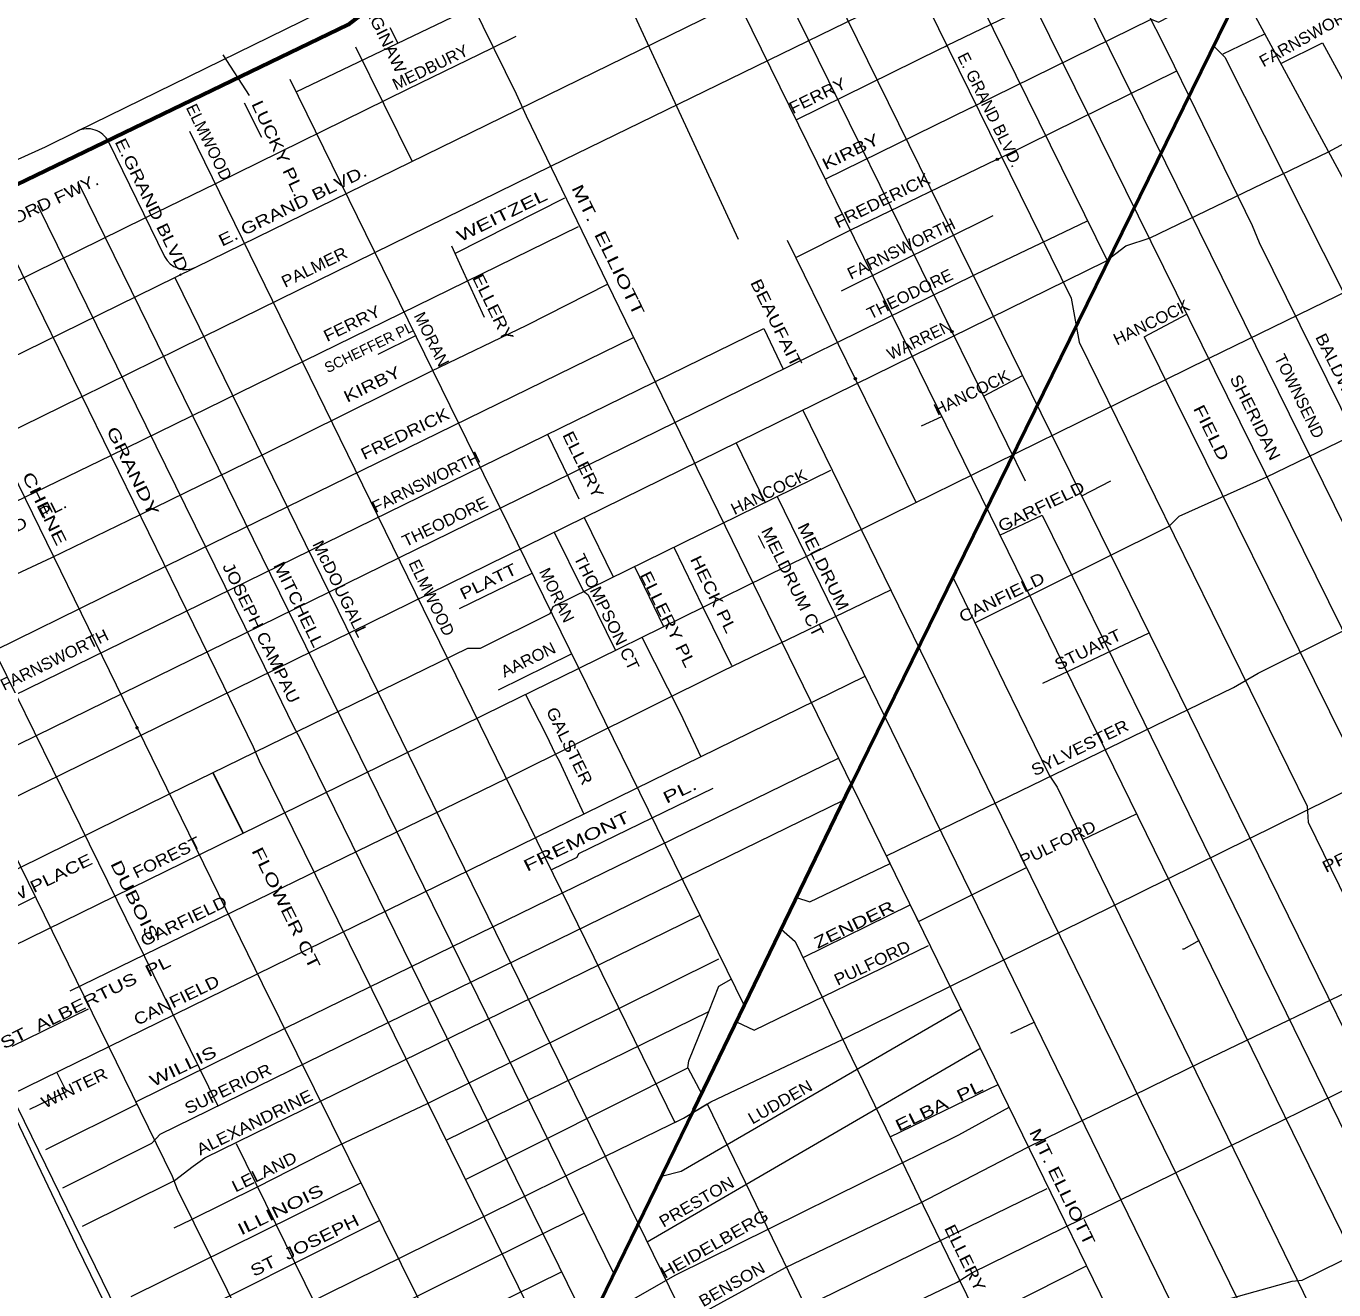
# Model space of a CAD drawing. Extents: x 34705 to 138605, y 34275 to 143551.
# Drawn here: x 100858 to 109243, y 108885 to 116985 of the extents above; entities that cross this region are included whole.
import ezdxf
from ezdxf.enums import TextEntityAlignment as Align

# ---------------------------------------------------------------- set-up
doc = ezdxf.new("R2010")
doc.units = 0
doc.header["$LTSCALE"] = 30
doc.header["$PDMODE"] = 32
doc.header["$PDSIZE"] = 15
for name, color, linetype, lineweight in [('1', 7, 'Continuous', 13), ('11', 7, 'Continuous', 13), ('50', 7, 'Continuous', 13), ('51', 7, 'Continuous', 35)]:
    doc.layers.add(name, color=color, linetype=linetype, lineweight=lineweight)

msp = doc.modelspace()

# ---------------------------------------------------------------- linework, layer by layer
at = {"layer": '1'}
for p, q in [((101946.58, 115440.18), (106331.92, 117586.09)), ((105661.1, 117328.25), (106793.71, 115026.96)), ((105968.83, 117341.08), (107047.11, 115150.16)), ((103190.96, 116977.68), (103241.23, 116876.22)), ((108533.25, 116808.59), (108799.8, 116935.24)), ((102290.54, 116540.81), (102122.04, 116800.93)), ((102969.6, 116852.85), (103333.34, 116118.77)), ((105794.39, 116385.29), (106718.61, 116839.15)), ((106718.61, 116839.15), (106749.55, 116854.35)), ((106719.59, 116839.12), (106749.76, 116853.93)), ((108902.55, 116745.01), (109169.81, 116878.68)), ((109169.81, 116878.68), (109748.55, 115811.65)), ((102548.95, 116644.61), (104007.06, 113672.22)), ((102256.05, 116494.16), (102366.55, 116273.1)), ((105981.35, 116004.43), (106913.98, 116461.76)), ((106913.98, 116461.76), (106937.02, 116473.06)), ((106914.97, 116461.73), (106937.23, 116472.64)), ((101904.66, 116312.82), (103353.47, 113354.48)), ((100112.7, 115818.14), (100981.9, 116212.44)), ((101386.15, 116243.47), (101745.94, 115508.93)), ((107084.73, 116131.92), (107100.92, 116139.73)), ((107085.73, 116131.9), (107101.12, 116139.32)), ((101196.3, 115973.74), (102650.04, 113012.5)), ((103607.65, 115527.11), (104312.09, 115885.41)), ((100930.19, 115838.63), (102383.21, 112882.78)), ((106086.97, 115288.74), (107058.8, 115771.9)), ((107368.04, 115596.43), (107663.35, 115738.12)), ((100679.08, 115705.99), (102123.39, 112756.47)), ((105738.03, 115614.35), (106173.86, 114725.62)), ((107363.16, 115594.08), (107368.04, 115596.43)), ((107364.18, 115594.07), (107368.24, 115596.02)), ((100130.13, 115432.56), (101569.9, 112487.39)), ((101811.9, 115374.28), (102907.45, 113137.64)), ((108027.16, 114992.93), (108300.55, 115138.4)), ((99058.1, 111852.89), (105587.02, 115047.35)), ((99606.19, 115114.96), (101026.13, 112223.03)), ((105587.01, 115047.35), (105712.39, 114787.06)), ((103354.21, 114999.3), (103112.73, 114881.18)), ((106793.71, 115026.96), (107264.3, 114070.8)), ((106173.86, 114725.62), (106563.86, 113930.38)), ((106996.77, 114614.39), (107246.52, 114744.99)), ((106599.07, 114424.3), (106728.43, 114482.53)), ((104200.41, 114368.91), (104402.66, 113956.36)), ((107626.19, 113973.56), (107813.85, 114070.66)), ((104436.21, 113835.46), (104621.95, 113454.92)), ((107101.51, 113722.51), (107372.9, 113850.14)), ((105552.22, 113719.92), (105592.95, 113638.07)), ((104007.06, 113672.22), (105461.73, 110706.87)), ((105010.3, 113645.36), (105196.3, 113260.42)), ((103637.05, 113252.79), (104101.73, 113479.25)), ((104757.89, 113521.58), (104944.02, 113136.38)), ((105196.3, 113260.42), (105380.59, 112886.54)), ((102907.45, 113137.64), (106147.78, 106522.3)), ((107377.4, 112773.99), (108057.88, 113096.43)), ((102650.04, 113012.5), (104626.36, 108986.77)), ((103887.28, 112730.34), (104355.65, 112961.63)), ((101026.13, 112223.03), (102086.57, 110063.28)), ((107632.42, 111771.01), (107976.75, 111937.08)), ((100540.44, 111219.2), (100915.56, 111404.1)), ((100768.13, 110446.98), (101256.95, 110685.64)), ((107172.27, 110529.93), (107320.76, 110600.97)), ((104839.84, 109192.55), (106972.96, 110430.97)), ((105100.6, 110307.27), (105190.82, 110139.11)), ((106397.62, 109865.98), (107089.92, 110200.3)), ((100725.09, 110119.47), (101179.79, 109170.78)), ((101531.27, 108841.79), (103003.94, 109570.01)), ((102010.55, 108172.35), (104435.15, 109376.27)), ((101179.4, 109171.09), (101613.2, 108281.84)), ((102173.49, 107956.97), (104290.98, 109001.05)), ((106967.75, 108690.6), (107657.67, 109038.06))]:
    msp.add_line(p, q, dxfattribs=at)
at = {"layer": '1', "lineweight": 53}
msp.add_lwpolyline([(101368.9, 103017.54), (102548.84, 105055.11), (103212.24, 106184.42), (103282.07, 106324.13), (104294.63, 108304.78), (105138.43, 110039.49), (106145.17, 112117.65), (109289.05, 118526.78), (110743.87, 121478.11), (113275.26, 126686.61), (116465.7, 133274.74), (120395.18, 141348.71), (121157.51, 142914.61), (121243.66, 143093.14)], dxfattribs=at)
at = {"layer": '1'}
for points in [[(97901.79, 110686.48), (98842.55, 111139.22), (98862.73, 111098.07), (107780.39, 115477.93), (107908.41, 115576.89), (108065.53, 115629.28), (109209.03, 116179.38), (109744.4, 116470.44), (111059.56, 117168.98), (111717.14, 117524.08), (112237.97, 117804.95), (112528.94, 117956.3), (112895.56, 118183.33), (114356.2, 118957.54), (115440.05, 119549.85), (118204.21, 120894.54), (118954.9, 121010.96), (119176.03, 121069.18), (124515.25, 123674.15), (127785.69, 125298.26), (131565.33, 127169.77), (132886.31, 127821.74), (134611.73, 128667.27), (136181.01, 129472.15)], [(104185.08, 124073.75), (104223.43, 122615.86), (104268.31, 121493.57), (104255.49, 121416.61), (104255.49, 119729.96), (104281.13, 119653), (104289.14, 119164.01), (104417.36, 119029.34), (104616.1, 118785.64), (106525.24, 114896.44)], [(107093.68, 120071.85), (107271.88, 119733.17), (107451.38, 119386.86), (107483.44, 119386.86), (108611.78, 117283.36), (109600.68, 115452.42), (109632.74, 115381.87), (112625.09, 109812.1), (112669.97, 109715.9), (112990.52, 109138.72), (113028.98, 109061.76), (114009.65, 107228.03)], [(105452.74, 119529.55), (105596.99, 119231.34), (107558.77, 115242.39), (107610.06, 114960.22), (109071.78, 111984.52), (109078.19, 111881.91), (112490.46, 104910.87), (112500.77, 104893)], [(106487.07, 119496.74), (107193.34, 118060.95), (107225.4, 118016.06), (109967.72, 112447.88), (110019.01, 112409.4), (111921.48, 108574.36), (112510.11, 107358.72)], [(105878.29, 119360.93), (105888.69, 119340.37), (107789.36, 115482.34)], [(107502.96, 118190.33), (107879.32, 117406.82), (108174.23, 116823.22), (108719.17, 115707.34), (108764.05, 115598.31), (109632.03, 113841.19)], [(106930.17, 117914.26), (109698.45, 112306.79), (109762.56, 112281.14), (111357.31, 109081), (111966.36, 107830.44), (112261.27, 107227.61), (112786.97, 106156.61)], [(98591.48, 110019.15), (101972.73, 111675.24), (103913.46, 112629.92), (104399.38, 112868.59), (107744.02, 114513.07), (108442.33, 114856.52), (109593.1, 115416.81), (109662.93, 115434.27), (111475.65, 116416.6), (113895.62, 117691.33), (113960.58, 117560.28), (114431.85, 117790.4)], [(106749.55, 116854.35), (106762.01, 116860.46), (107881.43, 117402.65), (107850.93, 117465.93), (108368.14, 117727.82)], [(102588.74, 116563.5), (103688.16, 117090.41), (103782.53, 117113.69), (104439.72, 117429.24)], [(106937.02, 116473.06), (108071.35, 117029.28), (108117.91, 117011.81), (108408.87, 117163.16), (108496.16, 117343.62), (108565.21, 117370.18)], [(99706.11, 113869.83), (101213.31, 114609.12), (101993.1, 114993.32), (103092.94, 115534.69), (104221.89, 116087.7), (106526.05, 117211.1)], [(100981.9, 116212.44), (101185.44, 116312.18), (102725.35, 117066.76)], [(103716.27, 117128.42), (103999.04, 116550.67), (104063.15, 116409.58), (104582.45, 115338.59), (105127.85, 114217.1)], [(99063.27, 114497.09), (101620.66, 115755.89), (102074.57, 115977.1), (103308.26, 116582.5), (103843.63, 116844.45), (104000.75, 116920.13)], [(106941.51, 113161.42), (108186.29, 113781.05), (108250.3, 113843.63), (108808.95, 114093.94), (110000.45, 114671.7), (110029.55, 114706.63), (111065.38, 115242.18), (112765.01, 116171.96), (112671.78, 116345.48), (113215.62, 116620.34), (113267.99, 116649.45), (113413.47, 116730.94), (113861.43, 116960.74)], [(108471.24, 116859.6), (108544.47, 116786.35), (109300.97, 115285.68), (109326.61, 115234.37), (109679.22, 114548.17), (109717.69, 114477.62), (109826.67, 114246.75), (109890.78, 114124.9), (109948.48, 114015.88), (109956.3, 114000.84)], [(107100.92, 116139.73), (107122.81, 116150.28), (108235.38, 116698)], [(105797.18, 111399.32), (105881.84, 111371.09), (106397.49, 111617.75), (106373.8, 111666.25), (108599.46, 112744.89), (108756.58, 112838.02), (110526.23, 113718.79), (110435.99, 113886.75), (110981.01, 114179.81), (112552.22, 115006.41), (113442.57, 115466.29), (113477.48, 115507.04), (113710.26, 115640.92), (113785.91, 115623.46), (114362.02, 115915.98), (115147.62, 116317.64)], [(105792.86, 115502.55), (106145.17, 115678.76), (107084.73, 116131.92)], [(94488.85, 110734.99), (95680.61, 111417.66), (99893.78, 113504.55), (101400.98, 114232.2), (104399.38, 115702.05)], [(100256.03, 112111.83), (105022.04, 114446.13), (106948.23, 115394.98), (107363.16, 115594.08)], [(103584.9, 115577.5), (103646.44, 115441.2), (103793.89, 115120.54)], [(104051.67, 107444.7), (104825.64, 107904.58), (104918.75, 107939.5), (105320.28, 108183.99), (105966.22, 108521.62), (106827.48, 108934.92), (106920.59, 108993.14), (111031.93, 111010.18), (111770.98, 111376.91), (112521.67, 111784.39), (113970.67, 112564.43), (114040.5, 112512.04), (115093.8, 113076.69), (115128.71, 113117.44), (116414.78, 113815.98), (116887.6, 114070.66), (116969.07, 114143.43), (117091.27, 114347.17), (117143.65, 114399.56), (119333.43, 115468.66)], [(99525.71, 114254.03), (100963.08, 114958.39), (101942.38, 115438.2)], [(99796.9, 112975.88), (100475.71, 113324.1), (101022.73, 113580.23), (101587.2, 113853.82), (102372.8, 114238.02), (103455.19, 114773.57), (104067.68, 115067.54), (104585.45, 115332.39)], [(107047.11, 115150.16), (109204.8, 110766.04), (109884.37, 109380.81), (109910.02, 109316.68), (110621.64, 107867.31), (111784.35, 105496.46)], [(100240.76, 112780.89), (101761.78, 113527.84), (104751.75, 114990.46)], [(108027.16, 114992.93), (109412.77, 112189.81), (109485.89, 112133.55), (112518.61, 105917.79)], [(106525.24, 114896.44), (107151.66, 113620.34), (110698.58, 106384.29), (110724.22, 106326.57), (111285.17, 105210.68)], [(99622.96, 107156.95), (99848.68, 107262.79), (100188.92, 107440.65), (100537.2, 107693.33), (100968.9, 107962.79), (103779.62, 109348.23), (104572.5, 109741.16), (105072.96, 109985.65), (105247.54, 110090.43), (106097.16, 110492.09), (110265.23, 112549.88), (110957.73, 112899.15), (112028.48, 113475.45), (113105.05, 114057.56), (114210.72, 114761.93)], [(105838, 114523.9), (109374.69, 107291.74), (109999.77, 106037.98), (110044.65, 105954.61), (110041.44, 105944.98), (110594.62, 104809.15)], [(105410.48, 114313.93), (105596.68, 113932.88), (105674.36, 113970.97), (109022.08, 107118.58), (109054.14, 107041.62), (110256.75, 104612.72), (110148.21, 104549.61), (110451.51, 103928.7)], [(105127.85, 114217.1), (105159.44, 114152.16), (109198.39, 105884.06), (109204.8, 105813.52), (110220.52, 103795.66)], [(100226.54, 111297.46), (100811.78, 111587.93), (101777.78, 112065.26), (103689.42, 112998.11), (103770.89, 112998.11), (104218.98, 113219.31), (104236.44, 113265.88), (106017.14, 114139.06)], [(107372.9, 113850.14), (108025.17, 112524.83), (111534.66, 105353.51)], [(104244.57, 113741.28), (104428.58, 113366.56), (104460.64, 113340.9), (104633.74, 112988.18)], [(106799.91, 113452.41), (106840.73, 113369.76), (107129.23, 112773.34), (107417.73, 112183.33), (107469.02, 112106.37), (109733.71, 107458.48), (110333.15, 106230.37), (110944.91, 105012.82)], [(101140.57, 110802.07), (103942.56, 112164.22), (105329.01, 112855.49), (106401.67, 113371.24)], [(103353.47, 113354.48), (105016.75, 109958.19), (105072.96, 109985.65), (105223.97, 110076.29), (106336.04, 107787.44)], [(104805.15, 113068.1), (105050.45, 112584.15), (105184.58, 112302.39)], [(102383.21, 112882.78), (102570.99, 112500.78), (102615.86, 112417.41), (105211.22, 107124.24)], [(98669.87, 109111.42), (99598.45, 109567.98), (106238.13, 112818.1)], [(102123.39, 112756.47), (102314.54, 112366.11), (102353.01, 112276.32), (104302.15, 108320.24)], [(104058.81, 112701.31), (104191.37, 112443.07), (104249.07, 112321.22), (104274.72, 112276.32), (104351.65, 112109.58), (104433.27, 111934.63)], [(101569.9, 112487.39), (102370.64, 110849.41), (103928.52, 107702.17), (103999.04, 107541.84), (104409.35, 106714.55), (104422.17, 106611.94), (104800.42, 105880.85), (104851.71, 105823.13), (104922.23, 105656.39)], [(100983.44, 109783.36), (101568.05, 110075.8), (101560.63, 110090.91), (102522.65, 110563.4), (106067.4, 112293.49)], [(100612.15, 112021.77), (101795.25, 109613.28), (101827.31, 109529.91), (103325.88, 106499.72), (103383.58, 106422.76), (103466.93, 106249.61), (103498.98, 106159.82), (103498.98, 106057.21), (103479.75, 105916.12), (103441.28, 105813.51), (103396.41, 105698.08), (103345.12, 105556.99), (103332.3, 105428.73), (103338.71, 105287.64), (103389.99, 105133.72), (103434.87, 104999.05), (103537.45, 104819.48), (103691.31, 104486), (105116.13, 101623.89), (105586.11, 101897.14), (106074.33, 100898.57)], [(101094.01, 109538.87), (101664.3, 109824.11), (101716.68, 109882.32), (103180.23, 110598.33), (106099.76, 112023.91)], [(104223.69, 111577.37), (104390.65, 111657.78), (104402.28, 111681.06), (105263.54, 112100.19)], [(101237.33, 105303.94), (101290.09, 105195.91), (101674.44, 105382.43), (101630.74, 105471.24), (103126.41, 106197.51), (103295.16, 106220.8), (103632.68, 106232.44), (104325.18, 106610.82), (106206.27, 107700.84), (106252.83, 107747.41), (108394.33, 108777.75), (108976.26, 108940.75), (109040.27, 108946.57), (111770.98, 110288.35), (114407.12, 111691.25), (114494.41, 111766.93), (114535.14, 111830.96), (114597.08, 112016.83)], [(105841.11, 111016), (106526.88, 111352.88), (106578.82, 111246.55), (107271.25, 111593.05)], [(101219.93, 109292.92), (101809.78, 109585.44), (101929.08, 109678.58), (102004.73, 109730.97), (105176.25, 111285.22)], [(105699.4, 111197.48), (105789.32, 111118.77), (106443.25, 109772.01), (106609.94, 109425.7), (107204.08, 108205.08)], [(108272.12, 111071.3), (108283.76, 111071.3), (108380.5, 111125.73)], [(105411.65, 110603.5), (105526.87, 110550.3), (106644.17, 111091.67)], [(101806.88, 109282.74), (101917.44, 109335.13), (102342.25, 109544.69), (102865.99, 109812.47), (102865.99, 109812.47), (103430.46, 110080.24), (105298.46, 111005.81)], [(103551.33, 109844.14), (105234.44, 110668.18), (105298.46, 110831.17), (105378.35, 110876.84)], [(104252.68, 108222.73), (105727.63, 109028.06), (106588.89, 109441.37), (107277.02, 109796.46), (108400.15, 110349.47), (109556.71, 110904.33)], [(104931.11, 109613.27), (105058.41, 109645.11), (106852.52, 110686.26)], [(103675.73, 109591.65), (105100.6, 110307.27), (105106.42, 110353.84), (105234.44, 110668.18)], [(100880.89, 110042.04), (101117.26, 110157.17), (101054.5, 110280.72)], [(104476.48, 108684.61), (104616.14, 108748.65), (105023.5, 108981.49), (106838.09, 109878.74), (107160.54, 110055.73)], [(102204.57, 109822.95), (103588.74, 107006.36), (103652.85, 106865.27), (103894.54, 106375.52)], [(104015.09, 107757.98), (104697.61, 108149.07), (105203.89, 108434.3), (105855.65, 108777.75), (106734.37, 109208.52), (107405.05, 109534.51)], [(101719.59, 108624.95), (101719.59, 108624.95), (103122.87, 109329.75)]]:
    msp.add_lwpolyline(points, dxfattribs=at)
for centre, start, end in [((101251.44, 116177.48), 26.09655, 116.10569), ((101880.65, 115574.91), 206.09656, 296.07426)]:
    msp.add_arc(centre, 150, start, end, dxfattribs=at)
for p in [(107084.73, 116131.92), (106793.71, 115026.96), (106173.86, 114725.62), (101569.9, 112487.39)]:
    msp.add_point(p, dxfattribs=at)
at = {"layer": '11', "lineweight": 25}
msp.add_line((102054.07, 112200.09), (102249.24, 111811.27), dxfattribs=at)
at = {"layer": '50'}
msp.add_line((104191.16, 118276.66), (105422.93, 115620.86), dxfattribs=at)
msp.add_lwpolyline([(104963.65, 101619.2), (103401.8, 104785.56), (102889.39, 105786.76), (100756.78, 110147.71), (99981.01, 111714.94)], dxfattribs=at)
at = {"layer": '51', "lineweight": 60}
msp.add_lwpolyline([(89988.97, 108477.92), (90798.22, 108939.62), (92566.47, 110548.39), (93464.95, 111299.42), (94105.99, 111757.01), (95119.35, 112339.78), (95250.63, 112499.83), (96676.31, 113207.77), (97328.93, 113874.92), (97846.67, 114327.24), (98207.01, 114625.98), (98499.02, 114825.57), (98833.46, 115013.44), (99483.55, 115334.66), (102925.69, 116996.78), (103558.52, 117486.18), (103681.6, 117588.78), (104071.36, 118187.96), (104132.9, 118380.85), (104301.11, 118680.44), (104522.65, 118930.79), (104875.48, 119181.13), (105281.64, 119320.67), (105414.65, 119357.96)], dxfattribs=at)

# ---------------------------------------------------------------- texts
at = {"layer": '1', "width": 1.45}
msp.add_text('GRANDY                                             ', height=75, rotation=296.284, dxfattribs=at).set_placement((101911.04, 113300.56), align=Align.CENTER)
at = {"layer": '11'}
for s, rotation, width, p in [('SAGINAW', 296.064, 1.15, (103112.19, 116920.66)), ('FARNSWORTH', 29.199, 1.05, (109120.85, 116904.44)), ('MEDBURY', 26.024, 1.05, (103465.83, 116688.22)), ('FERRY', 26.061, 1.15, (105948.93, 116506.63)), ('LUCKY PL.', 294.949, 1.3, (102441.17, 116184.85)), ('KIRBY', 26.061, 1.3, (106160.77, 116147.3)), ('E.GRAND BLVD.', 296.061, 1.25, (101637, 115808.86)), ('E. GRAND BLVD.', 26.061, 1.3, (102582.94, 115800.42)), ('FREDERICK', 26.061, 1.15, (106362.52, 115834.45)), ('EDSEL FORD FWY.', 25.693, 1.2, (100834.44, 115735.15)), ('MT.  ELLIOTT', 296.15, 1.45, (104555.58, 115534.02)), ('WEITZEL  ', 26.063, 1.45, (103961.21, 115755.57)), ('FARNSWORTH', 26.061, 1.05, (106485.29, 115525.19)), ('PALMER', 26.061, 1.1, (102721.82, 115407.09)), ('ELLERY', 296.064, 1.2, (103818.45, 115165.45)), ('THEODORE', 26.061, 1.05, (106540.33, 115234.46)), ('BEAUFAIT', 296.149, 1.25, (105634.13, 115066.48)), ('HANCOCK', 26, 1.05, (108088.59, 115053.03)), ('FERRY', 26.063, 1.15, (102963.57, 115045.61)), ('BALDWIN', 296.238, 1.15, (109237.84, 114757.05)), ('KIRBY', 26.062, 1.3, (103092.7, 114656.53)), ('HANCOCK', 26, 1.05, (106937.85, 114602.35)), ('SHERIDAN', 296.24, 1.15, (108705, 114460.78)), ('FREDRICK', 26.063, 1.2, (103303.27, 114338.33)), ('FIELD', 296.236, 1.35, (108423.44, 114362.7)), ('ELLERY', 296.064, 1.2, (104395.77, 114158.1)), ('FARNSWORTH', 26.061, 1.05, (103438.06, 114029.39)), ('CHENE                                           ', 296.282, 1.45, (101327.23, 113097.08)), ('HANCOCK', 26, 1.05, (105636.61, 113965.36)), ('GARFIELD', 25.999, 1.2, (107383.37, 113872.17)), ('THEODORE', 26.062, 1.05, (103560.15, 113775.97)), ('MELDRUM ', 296.215, 1.2, (105943.34, 113489.85)), ('MELDRUM CT', 296.215, 1.15, (105738.18, 113407.06)), ('McDOUGALL', 296.062, 1.1, (102839.34, 113362.66)), ('THOMPSON CT', 296.13, 1.1, (104546.67, 113213.54)), ('JOSEPH CAMPAU', 296.064, 1.15, (102331.4, 113080.18)), ('MITCHELL', 296.062, 1.2, (102571.87, 113261.81)), ('PLATT', 26, 1.25, (103837.68, 113392.43)), ('HECK PL', 296.13, 1.25, (105230.88, 113327.42)), ('ELLERY PL', 296.13, 1.25, (104938.31, 113167.4)), ('CANFIELD', 25.993, 1.2, (107130.05, 113290.07)), ('FARNSWORTH', 26.061, 1.05, (101055.49, 112889.58)), ('STUART', 26.217, 1.15, (107682.4, 112955.03)), ('AARON', 26, 1.05, (104093.32, 112890.82)), ('GALSTER', 296.061, 1.15, (104308.14, 112354.75)), ('SYLVESTER', 26.214, 1.15, (107630.28, 112325.97)), ('FREMONT      PL.            ', 26, 1.5, (104843.74, 111941.11)), ('PULFORD', 26.147, 1.1, (107489.6, 111713.53)), ('PRESTON ', 25.997, 1.25, (109479.45, 111696.69)), ('FOREST', 26.259, 1.15, (101775.67, 111623.29)), ('FLOWER CT                                     ', 296.282, 1.45, (102821.75, 110645.59)), ('WARSAW PLACE    ', 26.213, 1.3, (100877.66, 111413.67)), ('DUBOIS                                            ', 296.282, 1.45, (101913.07, 110569.02)), ('GARFIELD', 25.999, 1.2, (101884.9, 111215.08)), ('ZENDER  ', 26.129, 1.35, (106216.37, 111209.2)), ('PULFORD', 25.582, 1.1, (106299.17, 110946.41)), ('ST  ALBERTUS  PL', 26.489, 1.35, (101254.54, 110694.22)), ('CANFIELD', 25.999, 1.2, (101838.67, 110707.49)), ('WILLIS', 25.847, 1.4, (101880.28, 110284.51)), ('WINTER', 25.847, 1.15, (101183.11, 110145.28)), ('SUPERIOR', 25.846, 1.15, (102168.67, 110139.62)), ('LUDDEN', 29.835, 1.1, (105710.99, 110056.27)), ('ELBA  PL', 25.944, 1.4, (106727.38, 110031.27)), ('ALEXANDRINE', 26.215, 1.15, (102339.11, 109924.19)), ('MT. ELLIOTT', 296.13, 1.35, (107468.09, 109528.25)), ('LELAND', 26.285, 1.15, (102401.72, 109607.47)), ('PRESTON', 30.089, 1.1, (105175.2, 109416.08)), ('ILLINOIS', 26.288, 1.45, (102505.19, 109364.79)), ('ST  JOSEPH', 26.286, 1.3, (102660.14, 109135.43)), ('HEIDELBERG', 29.627, 1.2, (105289.94, 109146.77)), ('ELLERY', 296.13, 1.2, (106844.23, 109073.19)), ('BENSON', 29.774, 1.1, (105401.49, 108887.87))]:
    msp.add_text(s, height=75, rotation=rotation, dxfattribs=dict(at, width=width)).set_placement(p, align=Align.CENTER)
for s, height, rotation, p in [('E. GRAND BLVD.   ', 75, 296.238, (107022.69, 116395.19)), ('ELMWOOD', 75, 296.062, (101997.2, 116225.72)), ('MORAN', 75, 296.061, (103424.16, 114962.02)), ('SCHEFFER PL', 67.21, 26.062, (103069.72, 114896.08)), ('WARREN', 75, 26.061, (106601.29, 114940.98)), ('TOWNSEND', 75, 296.238, (108987.93, 114597.18)), ('ELMWOOD', 75, 296.062, (103424.23, 113305.21)), ('MORAN', 75, 296.061, (104226.6, 113321.73))]:
    msp.add_text(s, height=height, rotation=rotation, dxfattribs=at).set_placement(p, align=Align.CENTER)
at = {"layer": '11', "width": 1.25}
msp.add_text('HOMESTEAD   PL.', height=71.9, rotation=26.402, dxfattribs=at).set_placement((100192.06, 113440.22))

doc.saveas('drawing.dxf')
